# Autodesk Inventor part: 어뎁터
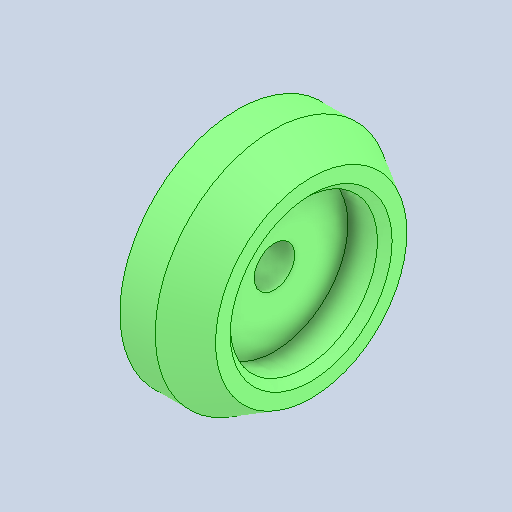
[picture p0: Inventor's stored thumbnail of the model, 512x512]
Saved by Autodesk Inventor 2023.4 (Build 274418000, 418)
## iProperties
Created: 2024-09
Part Number: 어뎁터
Material: 강철, 탄소
Document SubType Name: Modeling
Designer: 11
Density: 7.85 g/cm^3
Appearance: 기본값
Author: jhkim
Sending System: Autodesk Inventor 2025
Preprocessor: ST-DEVELOPER v20
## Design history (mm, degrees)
node "어뎁터1"
node "솔리드2"
node "솔리드1"
